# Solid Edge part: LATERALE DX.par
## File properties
Subject: LATERALE DX
Author: f_grande
Template: Normal.par
Last saved by: f_grande
Revision: 22
Application: Solid Edge
Densità: 750,000 kg/m^3
Precisione: 0,990
Tipo di contenuto documento: 0
Document Number: KR0116
Material: MDF
Stile della faccia: Marroncino
Coef. of Thermal Exp: 0.0
Thermal Conductivity: 0.0
Specific Heat: 0.0
Modulus of Elasticity: 0.0
Poisson's Ratio: 0.0
Yield Stress: 0.0
Ultimate Stress: 0.0
Elongation: 0.0
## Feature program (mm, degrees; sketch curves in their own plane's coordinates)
sketch for "unnamed Protrusion 1" plane through (0, 0, 0) normal (0, -1, 0) x-axis (1, 0, 0)
  line (-31.1402, -42.2949) -> (158.8598, -42.2949)
  line (158.8598, 45.2051) -> (158.8598, -42.2949)
  line (158.8598, 45.2051) -> (41.5285, 477.7051)
  line (41.5285, 477.7051) -> (-45.4715, 477.7051)
  line (-106.4715, 384.7051) -> (-45.4715, 477.7051)
  line (-106.4715, 384.7051) -> (-106.4715, 314.7051)
  line (-106.4715, 314.7051) -> (-31.1402, 198.7051)
  line (-31.1402, -42.2949) -> (-31.1402, 198.7051)
  dimension (linear) = 31.1402
  dimension (linear) = 41.5285
  dimension (linear) = 106.4715
  dimension (linear) = 158.8598
  dimension (linear) = 31.1402
  dimension (linear) = 106.4715
extrude "unnamed Protrusion 1" add finite 19 along +normal
fillet "Rotondo_1" radius 5
sketch for "Foro_1" plane through (25.7098, -19, 217.2051) normal (0, -1, 0) x-axis (1, 0, 0)
  hole centre (-98.7813, 132.4938) bore radius 10
hole "Foro_1" diameter 20 through
sketch for "Foro_8" plane through (25.7098, 0, 217.2051) normal (0, 1, 0) x-axis (-1, 0, 0)
hole "Foro_8" diameter 9 through
sketch for "unnamed Hole 1" plane through (25.7098, 0, 217.2051) normal (0, 1, 0) x-axis (-1, 0, 0)
hole "unnamed Hole 1" through
sketch for "unnamed Hole 2" plane through (25.7098, 0, 217.2051) normal (0, 1, 0) x-axis (-1, 0, 0)
  hole centre (-15.6, -203.9) bore radius 4.5
hole "unnamed Hole 2" through
sketch for "unnamed Hole 3" plane through (25.7098, 0, 217.2051) normal (0, 1, 0) x-axis (-1, 0, 0)
hole "unnamed Hole 3" through
pattern "unnamed Pattern 1" of "Foro_8", "unnamed Hole 1", "unnamed Hole 2", "unnamed Hole 3"
sketch for "Foro_12" plane through (25.7098, 0, 217.2051) normal (0, 1, 0) x-axis (-1, 0, 0)
hole "Foro_12" diameter 9 through
sketch for "unnamed Hole 4" plane through (25.7098, 0, 217.2051) normal (0, 1, 0) x-axis (-1, 0, 0)
hole "unnamed Hole 4" through
pattern "unnamed Pattern 2" of "Foro_12", "unnamed Hole 4"
fillet "Rotondo_4" radius 50
sketch for "Foro_18" plane through (26.1942, 0, 217.7051) normal (0, 1, 0) x-axis (-1, 0, 0)
  hole centre (98.6656, 155.5638) bore radius 2.5
hole "Foro_18" diameter 5 through
sketch for "unnamed Hole 5" plane through (26.1942, 0, 217.7051) normal (0, 1, 0) x-axis (-1, 0, 0)
  hole centre (122.2356, 131.9938) bore radius 2.5
hole "unnamed Hole 5" through
sketch for "unnamed Hole 6" plane through (26.1942, 0, 217.7051) normal (0, 1, 0) x-axis (-1, 0, 0)
  hole centre (99.2656, 108.4238) bore radius 2.5
hole "unnamed Hole 6" through
sketch for "unnamed Hole 7" plane through (26.1942, 0, 217.7051) normal (0, 1, 0) x-axis (-1, 0, 0)
hole "unnamed Hole 7" through
pattern "unnamed Pattern 3" of "Foro_18", "unnamed Hole 5", "unnamed Hole 6", "unnamed Hole 7"
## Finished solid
Body 1: solid body, 26 faces, 61 edges, 26 vertices.
  Faces by surface: cylinder 16, plane 10
  Edges by curve: circle 32, line 29
Bounding box of the edges (mm): 265.331 x 19.000 x 520.000, from (-106.4715, -19, -42.2949) to (158.8598, 0, 477.7051).
Cylindrical faces by radius (mm): R2.5 x4, R4.5 x6, R5 x4, R10 x1, R50 x1
Planar faces by outward normal: +x 1, +y 1, +z 1, -x 2, -y 1, -z 1, oblique 3
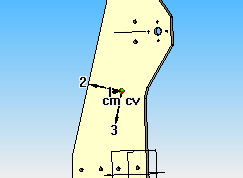
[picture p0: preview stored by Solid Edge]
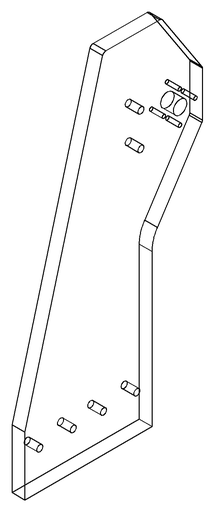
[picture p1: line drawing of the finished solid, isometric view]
